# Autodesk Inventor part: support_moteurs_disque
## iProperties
Created: 2011-01
Part Number: support_moteurs_disque
Document SubType Name: Modeling
Designer: eric
Density: 1 g/cm^3
Mass: 31.2071 g
Surface Area: 430.508 cm^2
Volume: 31.2071 cm^3
Author: eric
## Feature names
1. Base1
